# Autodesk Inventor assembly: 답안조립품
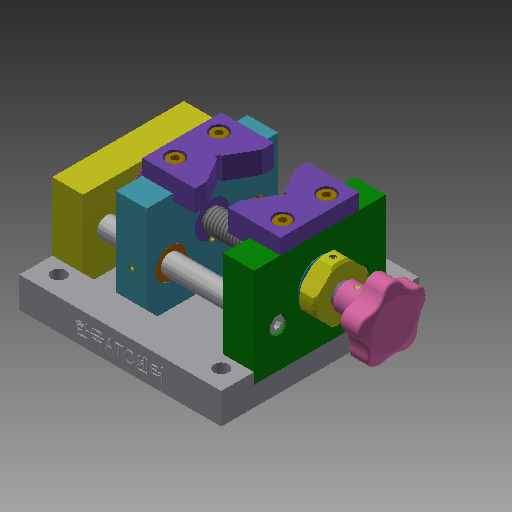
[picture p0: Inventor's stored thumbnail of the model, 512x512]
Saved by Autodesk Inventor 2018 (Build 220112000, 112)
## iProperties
Created: 2020-04
Part Number: 답안조립품
Document SubType Name: Assembly
Designer: Administrator
Mass: 773.761 g
Surface Area: 804.798 cm^2
Volume: 225.412 cm^3
Density: 3.43266 g/cm^3
Author: Administrator
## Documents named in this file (19)
- C:\Users\Administrator\Desktop\600407V1033\답안조립품.iam
- C:\Users\Administrator\Desktop\600407V1033\베이스.ipt
- C:\Users\Administrator\Desktop\600407V1033\고정 조.ipt
- C:\Users\Administrator\Desktop\600407V1033\이동 조.ipt
- C:\Users\Administrator\Desktop\600407V1033\서포트.ipt
- C:\Users\Administrator\Desktop\600407V1033\부시3.ipt
- C:\Users\Administrator\Desktop\600407V1033\부시1.ipt
- C:\Users\Administrator\Desktop\600407V1033\V블럭.ipt
- C:\Users\Administrator\Desktop\600407V1033\리드스크류.ipt
- C:\Users\Administrator\Desktop\600407V1033\부시너트.ipt
- C:\Users\Administrator\Desktop\600407V1033\멈춤나사 원추점 M3 x 5.ipt
- C:\Users\Administrator\Desktop\600407V1033\멈춤나사 납작점 M3 x 6.ipt
- C:\Users\Administrator\Desktop\600407V1033\부시2.ipt
- C:\Users\Administrator\Desktop\600407V1033\슬라이딩축.ipt
- C:\Users\Administrator\Desktop\600407V1033\볼트 M4 x 10.ipt
- C:\Users\Administrator\Desktop\600407V1033\너트.ipt
- C:\Users\Administrator\Desktop\600407V1033\손잡이.ipt
- C:\Users\Administrator\Desktop\600407V1033\핀 2 x 12.ipt
- C:\Users\Administrator\Desktop\600407V1033\볼트 M4 x 8.ipt
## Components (4 placed, 3 different names)
1. 고정 조:1 — 각도:6, 각도:7
2. V블럭:1
3. V블럭:2 — 각도:3
4. 핀 2 x 12:1
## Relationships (3: Angle 3)
- 각도:3 [Angle]: V블럭:2
- 각도:6 [Angle]: 고정 조:1
- 각도:7 [Angle]: 고정 조:1
